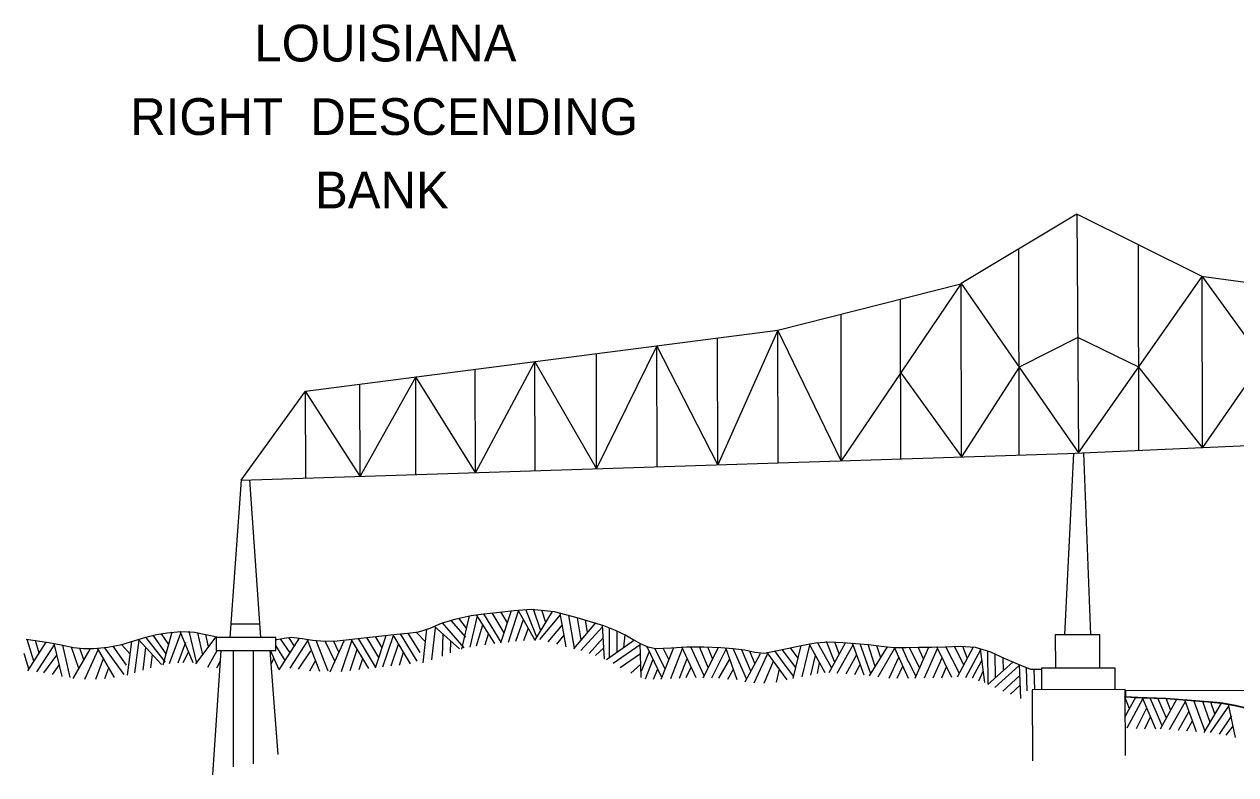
# Model space of a CAD drawing. Extents: x 3297716 to 3335574, y 688621 to 713991.
# Drawn here: x 3302199 to 3304936, y 699296 to 700992 of the extents above; entities that cross this region are included whole.
import ezdxf

# ---------------------------------------------------------------- set-up
doc = ezdxf.new("R2010")
doc.units = 0
doc.layers.add('V-ANNO-SYMB', color=7, linetype='Continuous')

msp = doc.modelspace()

# ---------------------------------------------------------------- linework, layer by layer
at = {"layer": 'V-ANNO-SYMB'}
for p, q in [((3304577.3, 700563.3), (3304581, 700023.6)), ((3304717, 700029.5), (3304716.2, 700494.2)), ((3304446.8, 700018.9), (3304446, 700484.4)), ((3304858.1, 700422.7), (3305540.6, 700332.5)), ((3304861.1, 700035.7), (3304860.4, 700422.4)), ((3303901.8, 700300.9), (3304315, 700405.9)), ((3304316.3, 700014.7), (3304315.6, 700406.1)), ((3304179.5, 700010.3), (3304178.9, 700371.3)), ((3304044.8, 700005.9), (3304044.2, 700337.1)), ((3302834.4, 700163.4), (3303901.8, 700300.9)), ((3303902.4, 700001.3), (3303901.8, 700300.9)), ((3303765.6, 699996.8), (3303765.1, 700283.3)), ((3303492, 699988), (3303491.5, 700248.1)), ((3303628.8, 699992.4), (3303628.3, 700265.7)), ((3303353.1, 699983.4), (3303352.7, 700230.2)), ((3303083.8, 699974.7), (3303083.4, 700195.5)), ((3303218.5, 699979.1), (3303218, 700212.8)), ((3302689.1, 699961.9), (3302834.4, 700163.4)), ((3302834.7, 699966.6), (3302834.4, 700163.4)), ((3302957.5, 699970.6), (3302957.1, 700179.2)), ((3304555.9, 700022.5), (3305736.3, 700073.8)), ((3302689.1, 699961.9), (3304555.9, 700022.5)), ((3304549.8, 699612.4), (3304570.1, 700023.1)), ((3304591.9, 700024), (3304608.2, 699612.5)), ((3302689.1, 699961.9), (3302663.2, 699606.3)), ((3302733.6, 699606.5), (3302708.9, 699962.5)), ((3303357.2, 699606.8), (3303332.3, 699669.5)), ((3303365.9, 699621.2), (3303349.3, 699670)), ((3303196.4, 699606.7), (3303163.1, 699645)), ((3303197.9, 699627.1), (3303181, 699649.8)), ((3303187.8, 699580), (3303204.5, 699654.9)), ((3303206.6, 699584.1), (3303222.6, 699655.3)), ((3303261.9, 699592.4), (3303220.5, 699657.3)), ((3303276.3, 699596), (3303237.5, 699659.5)), ((3303283.3, 699617.1), (3303256.2, 699661.6)), ((3303290.6, 699639.1), (3303275.5, 699663.9)), ((3303275.6, 699593.8), (3303299.5, 699666.9)), ((3303292.8, 699595.8), (3303315.9, 699666.4)), ((3303309.3, 699597.8), (3303327, 699646.7)), ((3303352.8, 699601.3), (3303315.1, 699668.1)), ((3303352.8, 699599.5), (3303392.5, 699665.2)), ((3303363.6, 699601.4), (3303410.6, 699657.6)), ((3303377.3, 699640.1), (3303368.3, 699667.9)), ((3303423.4, 699585.4), (3303410, 699661.1)), ((3303442.3, 699582.4), (3303429.4, 699655.9)), ((3303457.1, 699600.6), (3303448.9, 699650.7)), ((3303471.2, 699617.8), (3303466.8, 699645.8)), ((3302525.2, 699590.6), (3302508.7, 699614.8)), ((3302513, 699544.8), (3302532.8, 699619)), ((3302527, 699547.6), (3302552.6, 699616.2)), ((3302580.3, 699548.6), (3302550.8, 699619.5)), ((3302588.6, 699548.1), (3302571.2, 699620.6)), ((3302602.6, 699567.3), (3302590.9, 699616.7)), ((3302665.4, 699636.8), (3302731.5, 699637)), ((3303093.2, 699572.3), (3303066.1, 699616.2)), ((3303105.1, 699596.1), (3303085.3, 699617.5)), ((3303099.8, 699549), (3303108.4, 699625.2)), ((3303119.5, 699555.5), (3303127.9, 699628.3)), ((3303182.4, 699580.4), (3303125.2, 699631.7)), ((3303192.9, 699583.2), (3303143.8, 699639.3)), ((3303220.3, 699587), (3303235.1, 699634.5)), ((3303327.6, 699599.3), (3303337.9, 699627.7)), ((3303382.8, 699596.3), (3303414.8, 699634.5)), ((3303440.4, 699580.8), (3303489.9, 699639.4)), ((3303456, 699576.6), (3303505.6, 699630.1)), ((3303509.6, 699557.2), (3303505.3, 699634.1)), ((3303521.5, 699561.2), (3303521.4, 699628.3)), ((3303538.4, 699573.1), (3303538.5, 699620.4)), ((3302220.6, 699552.5), (3302205.5, 699601.8)), ((3302206.9, 699531.2), (3302248.5, 699595.7)), ((3302232.6, 699571.1), (3302224.3, 699599.1)), ((3302227.5, 699528.3), (3302267.4, 699589.8)), ((3302284.5, 699517.9), (3302266.2, 699592.5)), ((3302302.7, 699515.9), (3302285.9, 699588.6)), ((3302438.4, 699568.4), (3302419, 699590)), ((3302432.1, 699521.1), (3302442, 699597.4)), ((3302448.6, 699526.3), (3302458.2, 699600)), ((3302508.8, 699545.4), (3302456.9, 699601.9)), ((3302495.3, 699579), (3302473.4, 699607.2)), ((3302519.5, 699569.2), (3302490, 699611.5)), ((3302546.8, 699549.1), (3302564.2, 699595.9)), ((3302586.6, 699546.6), (3302632.6, 699608)), ((3302615.2, 699585.4), (3302609.1, 699613)), ((3302767, 699606.5), (3302632.2, 699606.2)), ((3302632.2, 699606.2), (3302632.2, 699576.6)), ((3302767.1, 699576.8), (3302767, 699606.5)), ((3302788.3, 699554.1), (3302767, 699588.1)), ((3302774.7, 699533.2), (3302820.9, 699604.5)), ((3302799.4, 699571.2), (3302777.9, 699603.2)), ((3302809.4, 699586.7), (3302796.8, 699606.1)), ((3302799.7, 699537.2), (3302839.8, 699598.5)), ((3302866.4, 699529.1), (3302838.6, 699600.7)), ((3302885.5, 699529.8), (3302858.6, 699599.4)), ((3302900.7, 699552.5), (3302878.7, 699598.1)), ((3302890.3, 699528.7), (3302921.3, 699598.9)), ((3302909.4, 699572.9), (3302897.3, 699598.5)), ((3302915.8, 699529.7), (3302939.2, 699598.8)), ((3302977.3, 699536.3), (3302937.4, 699602.1)), ((3302992.8, 699540.2), (3302954.3, 699603.9)), ((3303000, 699561.2), (3302973.1, 699605.9)), ((3302992.1, 699538), (3303016.5, 699610.9)), ((3303007.3, 699583.2), (3302992.4, 699608.1)), ((3303009.3, 699539.9), (3303032.8, 699610.4)), ((3303028.2, 699542), (3303044.5, 699591.4)), ((3303071.6, 699546.8), (3303032, 699612.4)), ((3303067.6, 699583.7), (3303049.2, 699614.3)), ((3303143.8, 699563.9), (3303145.3, 699613.7)), ((3303161.9, 699571.6), (3303162.6, 699598.1)), ((3303240.5, 699589.7), (3303248, 699614.2)), ((3303401.8, 699591.2), (3303418.7, 699611.5)), ((3303475, 699570.4), (3303506.9, 699605.2)), ((3303514.5, 699556.3), (3303577.4, 699600.6)), ((3303529.1, 699547.9), (3303590.1, 699590.3)), ((3303553.6, 699583.6), (3303556.3, 699612.5)), ((3303592.6, 699515.8), (3303590.7, 699592.5)), ((3303936.3, 699513.3), (3303954, 699588)), ((3303956.2, 699517.4), (3303973.7, 699588.6)), ((3304008.5, 699526.1), (3303972.3, 699591.6)), ((3304023.2, 699537), (3303991.4, 699594.8)), ((3304029.9, 699549.7), (3304011.5, 699596.9)), ((3304017.7, 699526.8), (3304054, 699594.4)), ((3304040.2, 699569.5), (3304030, 699595.9)), ((3304035.8, 699525.9), (3304071.4, 699589.6)), ((3304096.6, 699521), (3304070.2, 699593.2)), ((3304111.6, 699524.4), (3304087.2, 699591.7)), ((3304121.6, 699540.4), (3304105.9, 699590.1)), ((3304133.9, 699559.9), (3304125.3, 699587.6)), ((3304628.8, 699612.6), (3304528.4, 699612.4)), ((3304528.4, 699612.4), (3304528.6, 699537.3)), ((3304628.9, 699537.5), (3304628.8, 699612.6)), ((3302209.5, 699535.3), (3302198.8, 699570)), ((3302243.3, 699526.1), (3302272.7, 699566.3)), ((3302322.2, 699536.1), (3302305.5, 699584)), ((3302309.2, 699513.6), (3302348, 699579.9)), ((3302333.2, 699555.4), (3302324.1, 699582.2)), ((3302335.5, 699511.7), (3302365.8, 699578)), ((3302402.8, 699515.6), (3302364.2, 699582.2)), ((3302424.6, 699522.5), (3302381.3, 699583)), ((3302430, 699543.9), (3302399.8, 699586.5)), ((3302467.2, 699532.1), (3302473.4, 699583.8)), ((3302484.7, 699537.7), (3302488.3, 699567.7)), ((3302517.7, 699550.4), (3302495.3, 699579)), ((3302558.1, 699549.5), (3302570.1, 699573.1)), ((3302613.9, 699539.4), (3302635, 699576.6)), ((3302625, 699295.9), (3302644, 699576.6)), ((3302632.2, 699576.6), (3302767.1, 699576.8)), ((3302670.6, 699576.6), (3302671.1, 699314)), ((3302717.1, 699320.3), (3302716.5, 699576.7)), ((3302754.1, 699576.8), (3302771.6, 699341.7)), ((3302774.7, 699533.2), (3302755, 699576.8)), ((3302818.5, 699534.4), (3302846.2, 699575.8)), ((3302935.6, 699531.8), (3302951.4, 699579)), ((3303046.5, 699544), (3303055.9, 699572.7)), ((3303086.7, 699552.8), (3303067.7, 699583.7)), ((3303489.5, 699565.3), (3303508.1, 699583)), ((3303545.5, 699538.2), (3303591.3, 699570.3)), ((3303593.3, 699530.2), (3303611.2, 699575.5)), ((3303639.2, 699516.1), (3303606.5, 699585.4)), ((3303647.1, 699535.7), (3303623.2, 699581.4)), ((3303637.5, 699512.3), (3303666.7, 699583.3)), ((3303655.5, 699556.2), (3303642.2, 699582.3)), ((3303659.4, 699513.2), (3303686.3, 699581.3)), ((3303716.7, 699515.4), (3303684.6, 699585.2)), ((3303734.8, 699519.3), (3303704.7, 699585.1)), ((3303744.4, 699538.5), (3303724.8, 699585.3)), ((3303732.8, 699515.3), (3303767.4, 699583.9)), ((3303754.2, 699558.5), (3303743.4, 699584.7)), ((3303752, 699514.7), (3303785, 699579.8)), ((3303809.9, 699510.4), (3303783.6, 699582.7)), ((3303830.9, 699512.7), (3303800.6, 699581.2)), ((3303840.3, 699530.1), (3303819.4, 699579.9)), ((3303827.5, 699506.3), (3303862, 699570.3)), ((3303849.8, 699547.6), (3303838.4, 699575.5)), ((3303848.3, 699503.7), (3303878.2, 699568.3)), ((3303922.9, 699510.3), (3303877.7, 699572.3)), ((3303916, 699547), (3303894.7, 699575.7)), ((3303942.4, 699538.1), (3303911.4, 699579.2)), ((3303947.2, 699559.5), (3303930, 699583.1)), ((3303975.7, 699521.3), (3303986.6, 699565.8)), ((3304055.6, 699524.4), (3304079.8, 699567.9)), ((3304108.5, 699519.6), (3304149.3, 699584.8)), ((3304127.9, 699517.1), (3304165.3, 699581.4)), ((3304153, 699514.1), (3304174.9, 699561.4)), ((3304196.7, 699513.9), (3304164.8, 699583.7)), ((3304196.9, 699551.1), (3304182.2, 699583.6)), ((3304221.9, 699537.4), (3304199.2, 699583.7)), ((3304211.8, 699514.3), (3304242.7, 699584.5)), ((3304230.9, 699557.7), (3304218.3, 699584)), ((3304232.6, 699514.7), (3304262.2, 699581.6)), ((3304252.5, 699515), (3304272.6, 699560.6)), ((3304294.5, 699515.9), (3304260.7, 699584.9)), ((3304311.6, 699525.2), (3304280.8, 699585.3)), ((3304322, 699544.6), (3304300.9, 699586.1)), ((3304307.3, 699517.2), (3304343.4, 699584.9)), ((3304329.6, 699559.9), (3304319.4, 699586.2)), ((3304326.5, 699516.1), (3304360.9, 699580.4)), ((3304368.9, 699504.6), (3304359, 699580.9)), ((3304376.7, 699500.7), (3304375.6, 699576.4)), ((3304393.3, 699516.5), (3304392.8, 699568.7)), ((3304411.2, 699531.6), (3304410.5, 699560.7)), ((3302262.6, 699522.2), (3302278.1, 699543.6)), ((3302360.9, 699512), (3302377.7, 699558.8)), ((3302381.2, 699513.7), (3302389.8, 699537.9)), ((3302633.7, 699537.8), (3302642.4, 699553.2)), ((3302756.4, 699545.7), (3302762.8, 699559.3)), ((3302844.2, 699530.5), (3302856.7, 699553.8)), ((3302955.8, 699534), (3302963.8, 699558.4)), ((3303569.4, 699525.9), (3303591.8, 699546.1)), ((3303602.2, 699512.5), (3303619.8, 699557.2)), ((3303620.9, 699512.1), (3303630.1, 699535.4)), ((3303679.2, 699514.4), (3303696.7, 699558.8)), ((3303694.4, 699515.5), (3303705.5, 699539.5)), ((3303768.1, 699514.2), (3303792.8, 699557.3)), ((3303788.3, 699512.4), (3303801, 699534.7)), ((3303870.4, 699503.3), (3303892, 699552.5)), ((3303898.1, 699505.4), (3303905, 699534.8)), ((3303937.8, 699518.1), (3303916, 699547)), ((3303991.2, 699524.8), (3303995.6, 699549.3)), ((3304075.1, 699522.9), (3304087.7, 699545.2)), ((3304171.4, 699514), (3304184.1, 699541.4)), ((3304213.6, 699518.6), (3304197.7, 699551.2)), ((3304272.2, 699515.4), (3304282.7, 699539.6)), ((3304341.1, 699514.7), (3304362.5, 699554.1)), ((3304375.7, 699499.8), (3304432.8, 699551.3)), ((3304391.6, 699493), (3304446.8, 699542.7)), ((3304450.2, 699468.3), (3304447.1, 699545)), ((3304465.1, 699485.8), (3304463.1, 699538.4)), ((3304482.3, 699488.2), (3304480.5, 699534.6)), ((3304498.1, 699537.3), (3304662.8, 699537.6)), ((3304498.2, 699488.2), (3304498.1, 699537.3)), ((3304662.8, 699537.6), (3304662.9, 699488.5)), ((3304355.3, 699508.5), (3304365.5, 699530.2)), ((3304409.9, 699485), (3304448, 699520.5)), ((3304426.9, 699478), (3304448.9, 699498.6)), ((3304686.3, 699488.6), (3304476.2, 699488.2)), ((3304476.2, 699488.2), (3304476.6, 699327.3)), ((3304686.3, 699486.2), (3308343.2, 699494.5)), ((3304686.6, 699339.8), (3304686.3, 699488.6)), ((3304696.1, 699445.2), (3304685.8, 699472.3)), ((3304686.4, 699427.6), (3304710, 699471)), ((3304690.5, 699402.2), (3304726, 699467.5)), ((3304755.8, 699399.3), (3304725.5, 699469.8)), ((3304756.8, 699436.5), (3304742.8, 699469.3)), ((3304779.5, 699423.8), (3304759.9, 699468.9)), ((3304765.9, 699399.5), (3304803.3, 699466.5)), ((3304789, 699440.9), (3304778.9, 699468.3)), ((3304786.6, 699397.9), (3304822.4, 699461.8)), ((3304847.6, 699393.1), (3304821.2, 699465.2)), ((3304866.8, 699393.4), (3304841.2, 699463.5)), ((3304878.5, 699414.1), (3304861.3, 699461.8)), ((3304864.6, 699391.7), (3304903.7, 699457.7)), ((3304879.3, 699391.1), (3304920.6, 699451.3)), ((3304888.8, 699433.3), (3304879.8, 699460.1)), ((3304935.7, 699380.5), (3304919.8, 699455.8)), ((3304712.1, 699400.5), (3304735.1, 699447.3)), ((3304730.5, 699400), (3304743.8, 699427.1)), ((3304769.9, 699406.5), (3304756.8, 699436.5)), ((3304806.5, 699396.4), (3304830.8, 699439.9)), ((3304899, 699387.8), (3304926.9, 699429)), ((3304825.4, 699394.9), (3304838.4, 699417.9)), ((3304914.6, 699385.5), (3304930.3, 699405.8))]:
    msp.add_line(p, q, dxfattribs=at)
for points in [[(3304581, 700023.6), (3304860.4, 700422.4), (3304577.3, 700563.3), (3304315.6, 700406.1), (3304581, 700023.6)], [(3304860.4, 700422.4), (3305131, 700047.5), (3305263.7, 700369.1), (3305402.4, 700059.3)], [(3304315.6, 700406.1), (3304044.8, 700005.9), (3303901.8, 700300.9), (3303765.6, 699996.8), (3303628.3, 700265.7), (3303492, 699988), (3303352.7, 700230.2), (3303218.5, 699979.1), (3303083.4, 700195.5), (3302957.5, 699970.6), (3302834.4, 700163.4)], [(3304579.2, 700284.5), (3304446.4, 700217.5), (3304316.3, 700014.7)], [(3304716.7, 700217.4), (3304579.2, 700284.5)], [(3304997.2, 700232.4), (3304861.1, 700035.7), (3304716.7, 700217.4)], [(3304179.1, 700204.1), (3304316.3, 700014.7)], [(3302767.2, 699601.5), (3302769.5, 699601.5), (3302786.2, 699604.5), (3302802.9, 699607.1), (3302826.6, 699603.7), (3302850.4, 699599.9), (3302878, 699598.1), (3302905.5, 699598.6), (3302973.2, 699605.9), (3303041, 699613.4), (3303065.2, 699616.1), (3303089.4, 699618.9), (3303115.7, 699627.6), (3303141.4, 699638.6), (3303174.6, 699648.4), (3303208.4, 699655.7), (3303237.2, 699659.5), (3303266.1, 699662.8), (3303305.4, 699667.4), (3303344.7, 699670.5), (3303396.1, 699664.8), (3303447.2, 699651.2), (3303477.8, 699642.7), (3303507.9, 699633), (3303534, 699622.5), (3303559.4, 699610.7), (3303574.7, 699601.8), (3303590.1, 699592.8), (3303607.6, 699585.2), (3303625.9, 699581.6), (3303661, 699583.1), (3303696.1, 699585.2), (3303734.5, 699585), (3303772.9, 699583.7), (3303800, 699581.2), (3303827.1, 699578.2), (3303849.3, 699573), (3303871.3, 699571.1), (3303896.8, 699576.1), (3303922.3, 699581.6), (3303954.5, 699588.1), (3303986.8, 699594.5), (3304017.6, 699596.6), (3304048.6, 699594.8), (3304077.3, 699592.6), (3304106.1, 699590.1), (3304134.9, 699586.4), (3304163.7, 699583.7), (3304191.6, 699583.6), (3304219.6, 699584.1), (3304249.7, 699584.6), (3304279.7, 699585.2), (3304313.6, 699586.6), (3304347.4, 699584.7), (3304381.7, 699573.6), (3304414.7, 699558.9), (3304444.1, 699546.2), (3304472.4, 699534.5)], [(3302203.4, 699602.1), (3302228.8, 699598.5), (3302254.2, 699594.9), (3302282.1, 699589.4), (3302310, 699583.5), (3302332.9, 699581.3), (3302355.9, 699581.4), (3302387.8, 699584.2), (3302419.5, 699590.2), (3302446.8, 699598.7), (3302473.9, 699607.3), (3302497.7, 699612.8), (3302521.6, 699617), (3302552.6, 699619.5), (3302583.4, 699618.2), (3302608.8, 699613.1), (3302634.3, 699607.7), (3302640.2, 699607.2)], [(3304472.4, 699534.5), (3304498.1, 699534.6)], [(3308341.7, 699493.6), (3304686.7, 699485.7)], [(3304686.7, 699485.7), (3304686.7, 699472.9), (3304714.7, 699471.2), (3304778.1, 699469), (3304893.8, 699460), (3304906.6, 699458.3), (3304935.7, 699453), (3305022.5, 699432)], [(3304686.3, 699472.3), (3304723.5, 699469.9), (3304778.6, 699468.4), (3304825.7, 699464.8), (3304872.9, 699460.8), (3304903, 699457.8), (3304932.9, 699452.7), (3304965.8, 699445), (3304998.7, 699437.1), (3305025.3, 699430.5), (3305052, 699424), (3305078.7, 699424.7), (3305105.4, 699425.2), (3305140.8, 699415.7), (3305176.2, 699406.1), (3305214.9, 699396), (3305253.6, 699386.1), (3305280.3, 699384.5), (3305307.1, 699389), (3305350.6, 699402.9), (3305394.2, 699416.9), (3305435, 699426.1), (3305476.2, 699429.6)]]:
    msp.add_lwpolyline(points, dxfattribs=at)

# ---------------------------------------------------------------- texts
for s, height, p in [('LOUISIANA', 83, (3302718.8, 700908.3)), ('RIGHT  DESCENDING  ', 82.999, (3302438.3, 700742.2)), ('BANK', 83, (3302855.8, 700576.2))]:
    msp.add_text(s, height=height, rotation=0, dxfattribs=at).set_placement(p)

doc.saveas('drawing.dxf')
